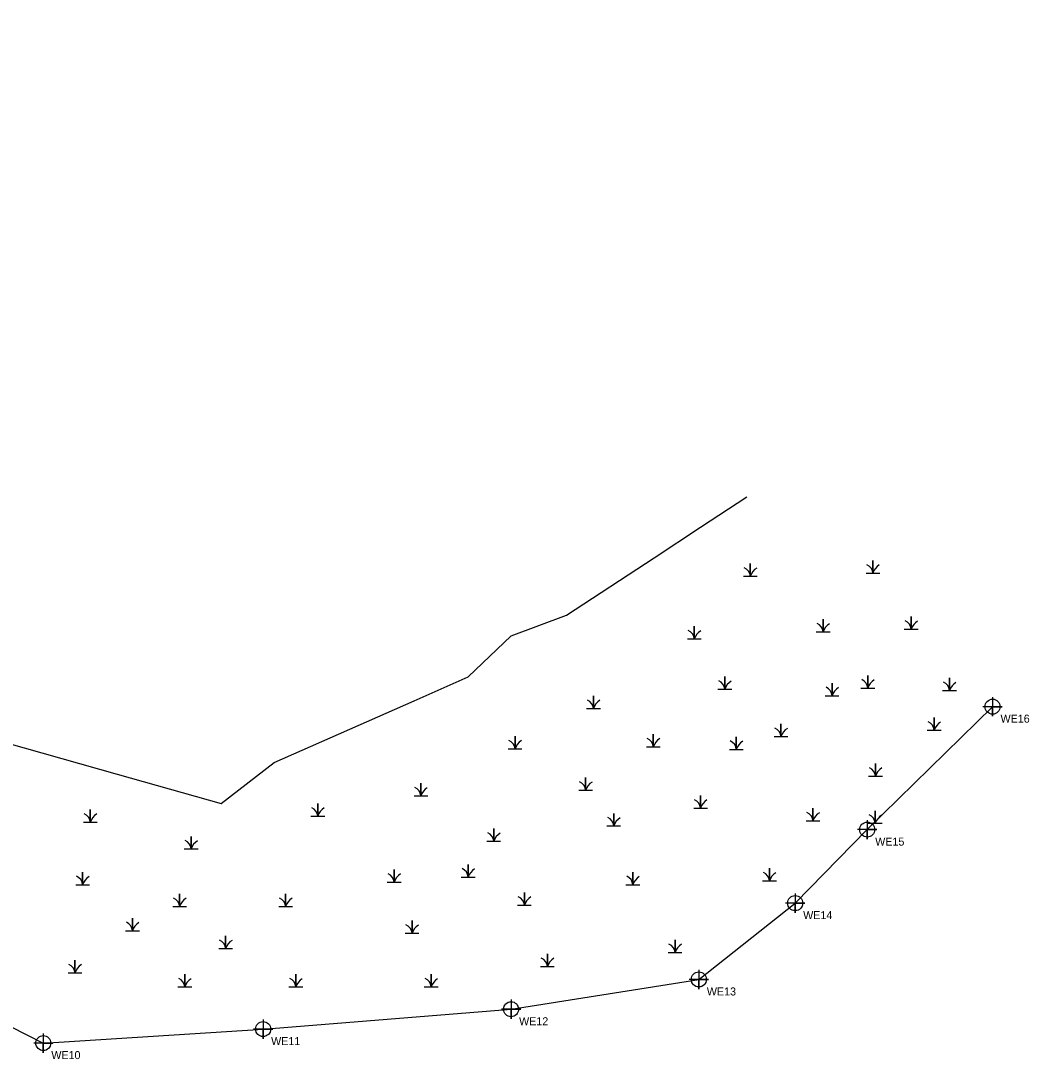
# Model space of a CAD drawing. Extents: x 2603618 to 2605510, y 618189 to 619022.
# Drawn here: x 2605195.6 to 2605510.4, y 618506.8 to 618831.1 of the extents above; entities that cross this region are included whole.
import ezdxf

# ---------------------------------------------------------------- set-up
doc = ezdxf.new("R2010")
doc.units = 0
for name, color, linetype in [('Exist Environmental Wetland Boundary', 7, 'Continuous'), ('Exist Environmental Wetland Boundary Cogo Comment', 7, 'Continuous'), ('Exist Environmental Wetland Boundary Cogo Point CELL', 7, 'Continuous'), ('Exist Hydro Jurisdictional Stream or Body of Water Mitigable', 7, 'Continuous'), ('Exist Hydro Swamp or Marsh', 7, 'Continuous')]:
    doc.layers.add(name, color=color, linetype=linetype)

# ---------------------------------------------------------------- blocks, each defined once
blk = doc.blocks.new('Exist Hydro Swamp or Marsh')
at = {"layer": 'Exist Hydro Swamp or Marsh'}
blk.add_line((0, 0), (0, 0), dxfattribs=at)
blk.add_lwpolyline([(-0.043, -0.0357), (0, -0.0357), (0, 0.0432), (0, -0.0357), (0.043, -0.0357)], dxfattribs=at)
for centre, radius, start, end in [((-0.0613, -0.0401), 0.0615, 4.14034, 67.53497), ((0.0912, -0.066), 0.0961, 122.12745, 161.62219)]:
    blk.add_arc(centre, radius, start, end, dxfattribs=at)

msp = doc.modelspace()

# ---------------------------------------------------------------- linework, layer by layer
at = {"layer": 'Exist Environmental Wetland Boundary'}
msp.add_lwpolyline([(2604888.21, 618831.09), (2604890.44, 618813.78), (2604921.62, 618750.94), (2604914.66, 618737.46), (2604913.79, 618700.35), (2604967.96, 618660.73), (2605045.97, 618600.08), (2605116.69, 618561), (2605136.62, 618545.44), (2605202.62, 618511.85), (2605271.25, 618516.23), (2605348.67, 618522.43), (2605407.29, 618531.73), (2605437.37, 618555.56), (2605459.86, 618578.52), (2605498.99, 618616.91)], dxfattribs=at)
at = {"layer": 'Exist Environmental Wetland Boundary Cogo Point CELL'}
for points in [[(2605498.99, 618619.91), (2605498.99, 618613.91), (2605498.99, 618616.91), (2605501.99, 618616.91), (2605495.99, 618616.91)], [(2605459.86, 618581.52), (2605459.86, 618575.52), (2605459.86, 618578.52), (2605462.86, 618578.52), (2605456.86, 618578.52)], [(2605437.37, 618558.56), (2605437.37, 618552.56), (2605437.37, 618555.56), (2605440.37, 618555.56), (2605434.37, 618555.56)], [(2605407.29, 618534.73), (2605407.29, 618528.73), (2605407.29, 618531.73), (2605410.29, 618531.73), (2605404.29, 618531.73)], [(2605348.67, 618525.43), (2605348.67, 618519.43), (2605348.67, 618522.43), (2605351.67, 618522.43), (2605345.67, 618522.43)], [(2605271.25, 618519.23), (2605271.25, 618513.23), (2605271.25, 618516.23), (2605274.25, 618516.23), (2605268.25, 618516.23)], [(2605202.62, 618514.85), (2605202.62, 618508.85), (2605202.62, 618511.85), (2605205.62, 618511.85), (2605199.62, 618511.85)]]:
    msp.add_lwpolyline(points, dxfattribs=at)
for centre in [(2605498.99, 618616.91), (2605459.86, 618578.52), (2605437.37, 618555.56), (2605407.29, 618531.73), (2605348.67, 618522.43), (2605271.25, 618516.23), (2605202.62, 618511.85)]:
    msp.add_circle(centre, 2.34, dxfattribs=at)
at = {"layer": 'Exist Hydro Jurisdictional Stream or Body of Water Mitigable'}
for points in [[(2605274.65, 618599.44), (2605318.39, 618618.76), (2605335.32, 618626.24), (2605348.69, 618639.02), (2605366.02, 618645.51), (2605393.33, 618663.43), (2605407.82, 618672.94), (2605422.31, 618682.45)], [(2605090.48, 618657.58), (2605116.3, 618638.53), (2605142.12, 618619.47), (2605173, 618610.74), (2605225.68, 618595.83), (2605258.13, 618586.65), (2605274.65, 618599.44)]]:
    msp.add_lwpolyline(points, dxfattribs=at)

# ---------------------------------------------------------------- block references
at = {"layer": 'Exist Hydro Swamp or Marsh', "xscale": 50, "yscale": 50}
for p in [(2605423.37, 618659.44), (2605461.64, 618660.41), (2605446.1, 618642.06), (2605473.6, 618642.86), (2605405.88, 618639.84), (2605415.4, 618624.12), (2605448.89, 618622.12), (2605460.05, 618624.51), (2605485.56, 618623.72), (2605374.39, 618618.14), (2605432.94, 618609.36), (2605480.77, 618611.35), (2605393.08, 618606.17), (2605349.9, 618605.53), (2605418.99, 618605.37), (2605462.44, 618597), (2605320.51, 618590.83), (2605371.95, 618592.61), (2605407.83, 618587.03), (2605288.32, 618584.53), (2605217.29, 618582.64), (2605380.72, 618581.44), (2605442.91, 618583.04), (2605462.36, 618582.27), (2605343.25, 618576.66), (2605248.78, 618574.26), (2605312.16, 618563.9), (2605335.28, 618565.49), (2605429.35, 618564.29), (2605214.9, 618563.1), (2605386.7, 618563.1), (2605245.19, 618556.32), (2605278.28, 618556.32), (2605352.82, 618556.72), (2605230.45, 618548.74), (2605317.74, 618547.94), (2605259.54, 618543.16), (2605399.86, 618541.96), (2605212.51, 618535.58), (2605360, 618537.57), (2605246.79, 618531.19), (2605281.47, 618531.19), (2605323.72, 618531.19)]:
    msp.add_blockref('Exist Hydro Swamp or Marsh', p, dxfattribs=at)

# ---------------------------------------------------------------- texts
at = {"layer": 'Exist Environmental Wetland Boundary Cogo Comment'}
for s, p in [('WE16', (2605501.49, 618611.91)), ('WE15', (2605462.36, 618573.52)), ('WE14', (2605439.87, 618550.56)), ('WE13', (2605409.79, 618526.73)), ('WE12', (2605351.17, 618517.43)), ('WE11', (2605273.75, 618511.23)), ('WE10', (2605205.12, 618506.85))]:
    msp.add_text(s, height=2.5, dxfattribs=at).set_placement(p)

doc.saveas('drawing.dxf')
